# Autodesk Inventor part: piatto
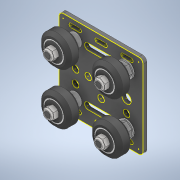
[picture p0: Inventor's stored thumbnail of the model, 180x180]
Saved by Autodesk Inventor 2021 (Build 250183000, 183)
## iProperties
Created: 2026-01
Part Number: piatto
Material: Generico
Document SubType Name: Modeling
Designer: hp
Density: 1 g/cm^3
Appearance: Default
Author: hp
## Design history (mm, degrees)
feature "Solido1"
feature "Solido2"
feature "Solido3"
feature "Solido4"
feature "Solido5"
feature "Solido6"
feature "Solido7"
feature "Solido8"
feature "Solido9"
feature "Solido10"
feature "Solido11"
feature "Solido12"
feature "Solido13"
feature "Solido14"
feature "Solido15"
feature "Solido16"
feature "Solido17"
feature "Solido18"
feature "Solido19"
feature "Solido20"
feature "Solido21"
feature "Solido22"
feature "Solido23"
feature "Solido24"
feature "Solido25"
feature "Solido26"
feature "Solido27"
feature "Solido28"
feature "Solido29"
sketch "Sketch1"
  geometry: L1 (-3.38, 62.12)-(-3.38, 3.38) reference; L2 (0, 0)-(58.74, 0) reference; L3 (62.12, 3.38)-(62.12, 62.12) reference; L4 (58.74, 65.5)-(0, 65.5) reference; L5 (39.69, 10.25)-(19.05, 10.25) reference; L6 (19.05, 15.25)-(39.69, 15.25) reference; L7 (32.62, 58.95)-(26.12, 58.95) reference; L8 (26.12, 61.95)-(32.62, 61.95) reference; L9 (5.97, 6.55)-(12.47, 6.55) reference; L10 (12.47, 3.55)-(5.97, 3.55) reference; L11 (32.62, 3.55)-(26.12, 3.55) reference; L12 (26.12, 6.55)-(32.62, 6.55) reference; L13 (46.27, 6.55)-(52.77, 6.55) reference; L14 (52.77, 3.55)-(46.27, 3.55) reference; L15 (5.97, 61.95)-(12.47, 61.95) reference; L16 (12.47, 58.95)-(5.97, 58.95) reference; L17 (52.77, 58.95)-(46.27, 58.95) reference; L18 (46.27, 61.95)-(52.77, 61.95) reference; L19 (19.05, 55.25)-(39.69, 55.25) reference; L20 (39.69, 50.25)-(19.05, 50.25) reference; C1 r 3.6 at (49.22, 52.75) reference; C2 r 2.5 at (49.22, 22.75) reference; C3 r 2.5 at (9.52, 52.75) reference; C4 r 2.5 at (9.52, 12.75) reference; C5 r 2.5 at (9.52, 32.75) reference; C6 r 2.5 at (29.37, 22.75) reference; C7 r 2.5 at (29.37, 42.75) reference; C8 r 2.5 at (29.37, 32.75) reference; C9 r 2.5 at (19.37, 32.75) reference; C10 r 2.5 at (39.37, 32.75) reference; C11 r 2.5 at (9.52, 22.75) reference; C12 r 2.5 at (9.52, 42.75) reference; C13 r 2.5 at (49.22, 42.75) reference; C14 r 3.6 at (49.22, 32.75) reference; C15 r 3.6 at (49.22, 12.75) reference; A1 r 3.38 centre (0, 62.12) between (0, 65.5) and (-3.38, 62.12) reference; A2 r 3.38 centre (0, 3.38) between (-3.38, 3.38) and (0, 0) reference; A3 r 3.38 centre (58.74, 3.38) between (58.74, 0) and (62.12, 3.38) reference; A4 r 3.38 centre (58.74, 62.12) between (62.12, 62.12) and (58.74, 65.5) reference; A5 r 2.5 centre (39.69, 12.75) between (39.69, 10.25) and (39.69, 15.25) reference; A6 r 2.5 centre (19.05, 12.75) between (19.05, 15.25) and (19.05, 10.25) reference; A7 r 1.5 centre (32.62, 60.45) between (32.62, 58.95) and (32.62, 61.95) reference; A8 r 1.5 centre (26.12, 60.45) between (26.12, 61.95) and (26.12, 58.95) reference; A9 r 1.5 centre (5.97, 5.05) between (5.97, 6.55) and (5.97, 3.55) reference; A10 r 1.5 centre (12.47, 5.05) between (12.47, 3.55) and (12.47, 6.55) reference; A11 r 1.5 centre (32.62, 5.05) between (32.62, 3.55) and (32.62, 6.55) reference; A12 r 1.5 centre (26.12, 5.05) between (26.12, 6.55) and (26.12, 3.55) reference; A13 r 1.5 centre (46.27, 5.05) between (46.27, 6.55) and (46.27, 3.55) reference; A14 r 1.5 centre (52.77, 5.05) between (52.77, 3.55) and (52.77, 6.55) reference; A15 r 1.5 centre (5.97, 60.45) between (5.97, 61.95) and (5.97, 58.95) reference; A16 r 1.5 centre (12.47, 60.45) between (12.47, 58.95) and (12.47, 61.95) reference; A17 r 1.5 centre (52.77, 60.45) between (52.77, 58.95) and (52.77, 61.95) reference; A18 r 1.5 centre (46.27, 60.45) between (46.27, 61.95) and (46.27, 58.95) reference; A19 r 2.5 centre (19.05, 52.75) between (19.05, 55.25) and (19.05, 50.25) reference; A20 r 2.5 centre (39.69, 52.75) between (39.69, 50.25) and (39.69, 55.25) reference; 1 further point
  node "Projected Loop1"
body "Solid1"
body "Solid2"
body "Solid3"
body "Solid4"
body "Solid5"
body "Solid6"
body "Solid7"
body "Solid8"
body "Solid9"
body "Solid10"
body "Solid11"
body "Solid12"
body "Solid13"
body "Solid14"
body "Solid15"
body "Solid16"
body "Solid17"
body "Solid18"
body "Solid19"
body "Solid20"
body "Solid21"
body "Solid22"
body "Solid23"
body "Solid24"
body "Solid25"
body "Solid26"
body "Solid27"
body "Solid28"
body "Solid29"
